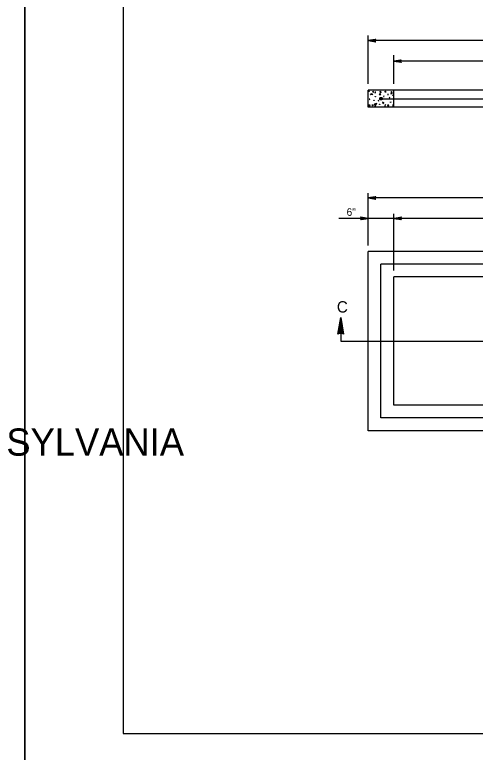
# Model space of a CAD drawing. Extents: x 2087776 to 2104538, y 970919 to 982612.
# Drawn here: x 2098799 to 2099399, y 976790 to 977750 of the extents above; entities that cross this region are included whole.
import ezdxf

# ---------------------------------------------------------------- set-up
doc = ezdxf.new("R2010")
doc.units = 0
doc.layers.add('1', color=7, linetype='Continuous')
doc.layers.add('PLT-BNDY', color=7, linetype='Continuous')

msp = doc.modelspace()

# ---------------------------------------------------------------- linework, layer by layer
at = {"layer": '1'}
for p, q in [((2099259.38, 977660.43), (2099259.38, 977723.33)), ((2099876.05, 977716.51), (2099259.38, 977716.51)), ((2099292.71, 977660.43), (2099292.71, 977697.52)), ((2099842.71, 977689.85), (2099292.71, 977689.85)), ((2099876.05, 977652.03), (2099259.38, 977652.03)), ((2099259.38, 977629.81), (2099259.38, 977652.03)), ((2099292.71, 977629.81), (2099292.71, 977652.03)), ((2099276.05, 977640.92), (2099859.38, 977640.92)), ((2099876.05, 977629.81), (2099259.38, 977629.81)), ((2099259.38, 977449.68), (2099259.38, 977517.87)), ((2099876.05, 977511.82), (2099259.38, 977511.82)), ((2099292.71, 977417.33), (2099292.71, 977491.21)), ((2099912.47, 977485.16), (2099220.94, 977485.16)), ((2099259.38, 977208.87), (2099259.38, 977442.21)), ((2099876.05, 977442.21), (2099259.38, 977442.21)), ((2099276.05, 977225.54), (2099276.05, 977425.54)), ((2099612.16, 977425.54), (2099276.05, 977425.54)), ((2099292.71, 977242.21), (2099292.71, 977408.87)), ((2099842.71, 977408.87), (2099292.71, 977408.87)), ((2099223.74, 977335.41), (2099223.74, 977325.54)), ((2099223.74, 977325.54), (2099259.38, 977325.54)), ((2099259.38, 977325.54), (2099876.05, 977325.54)), ((2099842.71, 977242.21), (2099292.71, 977242.21)), ((2099612.16, 977225.54), (2099276.05, 977225.54)), ((2099876.05, 977208.87), (2099259.38, 977208.87))]:
    msp.add_line(p, q, dxfattribs=at)
for points in [[(2101519.11, 976815.01), (2101519.11, 978665.4), (2098940.37, 978665.4), (2098940.37, 976815.01), (2101519.11, 976815.01), (2101519.11, 976901.49), (2100862.94, 976901.49), (2100862.94, 977113.68), (2101519.11, 977113.68), (2101519.11, 977208.71), (2100862.94, 977208.71), (2100862.94, 976815.01), (2101121.48, 976815.01), (2101121.48, 976901.49), (2101121.48, 976815.01), (2101374.1, 976815.01), (2101374.1, 976901.49), (2101374.1, 976861.08), (2101519.11, 976861.08)], [(2099259.38, 977716.51), (2099269.16, 977718.35), (2099268.79, 977718.09), (2099268.41, 977717.82), (2099268.22, 977717.5), (2099268.02, 977717.17), (2099267.97, 977716.84), (2099267.91, 977716.51), (2099267.97, 977716.18), (2099268.02, 977715.86), (2099268.22, 977715.53), (2099268.41, 977715.2), (2099268.79, 977714.94), (2099269.16, 977714.68), (2099259.38, 977716.51), (2099268.79, 977714.94), (2099268.41, 977715.2), (2099259.38, 977716.51), (2099268.22, 977715.53), (2099268.02, 977715.86), (2099259.38, 977716.51), (2099267.97, 977716.18), (2099267.91, 977716.51), (2099259.38, 977716.51), (2099267.97, 977716.84), (2099268.02, 977717.17), (2099259.38, 977716.51), (2099268.22, 977717.5), (2099268.41, 977717.82), (2099259.38, 977716.51), (2099268.79, 977718.09)], [(2099292.71, 977689.85), (2099302.5, 977691.68), (2099302.12, 977691.42), (2099301.74, 977691.16), (2099301.55, 977690.83), (2099301.36, 977690.5), (2099301.3, 977690.17), (2099301.24, 977689.85), (2099301.3, 977689.52), (2099301.36, 977689.19), (2099301.55, 977688.86), (2099301.74, 977688.53), (2099302.12, 977688.27), (2099302.5, 977688.01), (2099292.71, 977689.85), (2099302.12, 977688.27), (2099301.74, 977688.53), (2099292.71, 977689.85), (2099301.55, 977688.86), (2099301.36, 977689.19), (2099292.71, 977689.85), (2099301.3, 977689.52), (2099301.24, 977689.85), (2099292.71, 977689.85), (2099301.3, 977690.17), (2099301.36, 977690.5), (2099292.71, 977689.85), (2099301.55, 977690.83), (2099301.74, 977691.16), (2099292.71, 977689.85), (2099302.12, 977691.42)], [(2099260.86, 977650.82), (2099261.09, 977650.45), (2099260.64, 977650.3), (2099260.41, 977650.67), (2099260.71, 977650.82)], [(2099263.42, 977647.47), (2099265.23, 977646.4), (2099262.36, 977645.87), (2099263.32, 977647.15)], [(2099265.34, 977650.23), (2099265.44, 977650.66), (2099265.87, 977650.45), (2099265.76, 977648.75), (2099265.44, 977648.85)], [(2099268.31, 977650.38), (2099268.54, 977648.13), (2099268.99, 977650.3)], [(2099275.68, 977647.14), (2099273.55, 977646.72), (2099274.93, 977645.65), (2099275.57, 977646.18), (2099275.68, 977647.14)], [(2099275.46, 977650.49), (2099275.69, 977648.85), (2099275.24, 977648.7), (2099275.01, 977650.34), (2099275.31, 977650.49)], [(2099279.67, 977644.49), (2099279.14, 977643.63), (2099280.1, 977643.95)], [(2099281.48, 977650.76), (2099281.91, 977650.65), (2099281.7, 977648.95), (2099281.27, 977650.33), (2099281.38, 977650.65)], [(2099284.68, 977646.28), (2099285.65, 977646.51), (2099284.75, 977646.96)], [(2099289.94, 977650.45), (2099288.73, 977647.37), (2099290.47, 977647.59), (2099290.54, 977648.42), (2099289.94, 977650.45)], [(2099291.54, 977644.9), (2099291.12, 977645), (2099291.33, 977645.43), (2099291.75, 977645.32), (2099291.65, 977645)], [(2099261.54, 977640.35), (2099260.57, 977640.12), (2099261.47, 977639.67)], [(2099267.06, 977638.35), (2099266.63, 977638.46), (2099266.84, 977638.89), (2099267.27, 977638.78), (2099267.16, 977638.46)], [(2099267.98, 977634.37), (2099270.02, 977634.9), (2099268.36, 977631.22), (2099268.13, 977634.08)], [(2099268.74, 977643.41), (2099268.32, 977643.51), (2099268.53, 977643.94), (2099268.95, 977643.84), (2099268.85, 977643.51)], [(2099273.22, 977638.3), (2099272.37, 977638.83), (2099272.69, 977637.87)], [(2099274.89, 977641.62), (2099274.46, 977641.73), (2099274.67, 977642.16), (2099275.1, 977642.05), (2099275, 977641.73)], [(2099279.99, 977635.53), (2099278.18, 977636.49), (2099278.29, 977634.57), (2099279.89, 977635.42)], [(2099282.98, 977640.43), (2099282.6, 977640.2), (2099282.45, 977640.65), (2099282.83, 977640.88), (2099282.98, 977640.58)], [(2099286.65, 977642.35), (2099287.5, 977641.82), (2099287.18, 977642.78)], [(2099288.78, 977636.66), (2099289.01, 977636.28), (2099288.55, 977636.13), (2099288.33, 977636.51), (2099288.63, 977636.66)], [(2099260.8, 977631.7), (2099261.17, 977633.2), (2099261.32, 977631.47), (2099260.95, 977631.25), (2099260.8, 977631.55)], [(2099265.23, 977633.24), (2099265.46, 977631.59), (2099265, 977631.44), (2099264.78, 977631.82), (2099265.08, 977633.24)], [(2099274.45, 977633.61), (2099274.34, 977633.18), (2099273.92, 977633.39), (2099274.02, 977633.82), (2099274.34, 977633.71)], [(2099281.48, 977631.16), (2099282.01, 977633.28), (2099281.06, 977631.69)], [(2099285.58, 977633.14), (2099285.81, 977631.49), (2099285.36, 977631.34), (2099285.13, 977631.72), (2099285.43, 977633.14)], [(2099292.19, 977633.14), (2099292.42, 977631.49), (2099291.97, 977631.34), (2099291.74, 977631.72), (2099292.04, 977633.14)], [(2099259.38, 977511.82), (2099269.16, 977513.66), (2099268.79, 977513.4), (2099268.41, 977513.14), (2099268.22, 977512.81), (2099268.02, 977512.48), (2099267.97, 977512.15), (2099267.91, 977511.82), (2099267.97, 977511.5), (2099268.02, 977511.17), (2099268.22, 977510.84), (2099268.41, 977510.51), (2099268.79, 977510.25), (2099269.16, 977509.99), (2099259.38, 977511.82), (2099268.79, 977510.25), (2099268.41, 977510.51), (2099259.38, 977511.82), (2099268.22, 977510.84), (2099268.02, 977511.17), (2099259.38, 977511.82), (2099267.97, 977511.5), (2099267.91, 977511.82), (2099259.38, 977511.82), (2099267.97, 977512.15), (2099268.02, 977512.48), (2099259.38, 977511.82), (2099268.22, 977512.81), (2099268.41, 977513.14), (2099259.38, 977511.82), (2099268.79, 977513.4)], [(2099259.38, 977485.16), (2099249.59, 977483.32), (2099249.97, 977483.58), (2099250.35, 977483.84), (2099250.54, 977484.17), (2099250.74, 977484.5), (2099250.79, 977484.83), (2099250.85, 977485.16), (2099250.79, 977485.48), (2099250.74, 977485.81), (2099250.54, 977486.14), (2099250.35, 977486.47), (2099249.97, 977486.73), (2099249.59, 977486.99), (2099259.38, 977485.16), (2099249.97, 977486.73), (2099250.35, 977486.47), (2099259.38, 977485.16), (2099250.54, 977486.14), (2099250.74, 977485.81), (2099259.38, 977485.16), (2099250.79, 977485.48), (2099250.85, 977485.16), (2099259.38, 977485.16), (2099250.79, 977484.83), (2099250.74, 977484.5), (2099259.38, 977485.16), (2099250.54, 977484.17), (2099250.35, 977483.84), (2099259.38, 977485.16), (2099249.97, 977483.58)], [(2099292.71, 977485.16), (2099302.5, 977486.99), (2099302.12, 977486.73), (2099301.74, 977486.47), (2099301.55, 977486.14), (2099301.36, 977485.81), (2099301.3, 977485.48), (2099301.24, 977485.16), (2099301.3, 977484.83), (2099301.36, 977484.5), (2099301.55, 977484.17), (2099301.74, 977483.84), (2099302.12, 977483.58), (2099302.5, 977483.32), (2099292.71, 977485.16), (2099302.12, 977483.58), (2099301.74, 977483.84), (2099292.71, 977485.16), (2099301.55, 977484.17), (2099301.36, 977484.5), (2099292.71, 977485.16), (2099301.3, 977484.83), (2099301.24, 977485.16), (2099292.71, 977485.16), (2099301.3, 977485.48), (2099301.36, 977485.81), (2099292.71, 977485.16), (2099301.55, 977486.14), (2099301.74, 977486.47), (2099292.71, 977485.16), (2099302.12, 977486.73)], [(2099219.94, 977334.68), (2099223.74, 977356.18), (2099227.44, 977334.68), (2099226.95, 977334.92), (2099227, 977337.19), (2099226.53, 977339.97), (2099226.47, 977335.07), (2099225.97, 977335.17), (2099225.95, 977343.32), (2099225.46, 977346.21), (2099225.47, 977335.3), (2099224.92, 977335.41), (2099224.94, 977349.15), (2099224.38, 977352.43), (2099224.4, 977335.47), (2099223.91, 977335.44), (2099223.91, 977355.19), (2099223.73, 977356.15), (2099223.24, 977353.39), (2099223.38, 977335.51), (2099222.88, 977335.43), (2099222.76, 977350.64), (2099222.28, 977347.93), (2099222.28, 977335.34), (2099221.82, 977335.34), (2099221.74, 977344.86), (2099221.18, 977341.76), (2099221.24, 977335.17), (2099220.7, 977335.03), (2099220.73, 977339.19), (2099220.18, 977336.04), (2099220.3, 977334.83)]]:
    msp.add_lwpolyline(points, dxfattribs=at)
msp.add_arc((2099223.69, 977325.46), 9.95, 67.87619, 112.12381, dxfattribs=at)
msp.add_spline([(2099276.05, 977640.92), (2099275.96, 977640.75), (2099275.83, 977640.77), (2099275.8, 977641.04), (2099276.04, 977641.18), (2099276.33, 977641.04), (2099276.32, 977640.77), (2099276.16, 977640.61), (2099275.83, 977640.58), (2099275.61, 977640.75), (2099275.49, 977641.03), (2099275.66, 977641.39), (2099276.01, 977641.47), (2099276.41, 977641.35), (2099276.62, 977641.11), (2099276.59, 977640.69), (2099276.39, 977640.42), (2099276.04, 977640.32), (2099275.72, 977640.38), (2099275.46, 977640.54), (2099275.35, 977640.82), (2099275.28, 977641.17), (2099275.36, 977641.5), (2099275.67, 977641.71), (2099276.14, 977641.8), (2099276.66, 977641.59), (2099276.91, 977641.24), (2099276.91, 977640.75), (2099276.75, 977640.34), (2099276.39, 977640.06), (2099275.83, 977640.03), (2099275.43, 977640.25), (2099275.19, 977640.64), (2099275.04, 977641.04), (2099275.11, 977641.53), (2099275.43, 977641.87), (2099275.9, 977642.06), (2099276.64, 977641.95), (2099277.1, 977641.54), (2099277.2, 977640.97), (2099277.1, 977640.42), (2099276.78, 977639.98), (2099276.35, 977639.81), (2099275.67, 977639.82), (2099275.14, 977640.13), (2099274.88, 977640.58), (2099274.82, 977641.06), (2099274.87, 977641.47), (2099275.03, 977641.92), (2099275.46, 977642.23), (2099276.17, 977642.33), (2099276.8, 977642.16), (2099277.27, 977641.72), (2099277.46, 977641.21), (2099277.41, 977640.56), (2099277.2, 977639.95), (2099276.85, 977639.69), (2099276.22, 977639.47), (2099275.57, 977639.56), (2099275.12, 977639.77), (2099274.77, 977640.17), (2099274.59, 977640.59), (2099274.59, 977641.04), (2099274.61, 977641.53), (2099274.72, 977641.98), (2099274.95, 977642.23), (2099275.3, 977642.46), (2099275.66, 977642.59), (2099276.01, 977642.64), (2099276.46, 977642.58), (2099276.91, 977642.43), (2099277.3, 977642.14), (2099277.57, 977641.77), (2099277.7, 977641.32), (2099277.77, 977640.88), (2099277.67, 977640.38), (2099277.49, 977639.98), (2099277.17, 977639.62), (2099276.78, 977639.37), (2099276.39, 977639.22), (2099275.93, 977639.21), (2099275.4, 977639.34), (2099274.95, 977639.62), (2099274.67, 977639.9), (2099274.45, 977640.27), (2099274.37, 977640.66), (2099274.35, 977641.11), (2099274.45, 977641.59), (2099274.59, 977641.81), (2099274.88, 977642.14)], degree=3, dxfattribs=at)
at = {"layer": 'PLT-BNDY'}
for points in [[(2096053.23, 978714.61), (2098812.42, 978714.61), (2098812.42, 976765.79), (2096053.23, 976765.79)], [(2098812.42, 978714.61), (2101571.61, 978714.61), (2101571.61, 976765.79), (2098812.42, 976765.79)]]:
    msp.add_lwpolyline(points, close=True, dxfattribs=at)

# ---------------------------------------------------------------- texts
at = {"layer": '1'}
msp.add_text('6"', height=9.843, rotation=360, dxfattribs=at).set_placement((2099231.26, 977488.43))
for s, height, p in [('C', 14.76, (2099218.58, 977362.6)), ('COMMONWEALTH OF PENNSYLVANIA', 35.3785, (2098146.9, 977176.37))]:
    msp.add_text(s, height=height, dxfattribs=at).set_placement(p)

doc.saveas('drawing.dxf')
